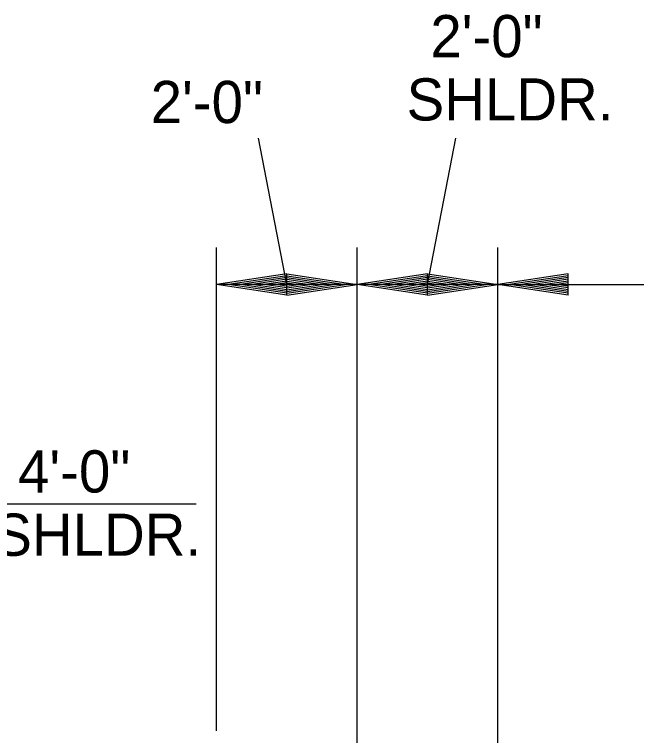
# Model space of a CAD drawing. Extents: x 2829243 to 2838161, y 467639 to 474695.
# Drawn here: x 2833956.1 to 2834044.6, y 469093.4 to 469196 of the extents above; entities that cross this region are included whole.
import ezdxf

# ---------------------------------------------------------------- set-up
doc = ezdxf.new("R2010")
doc.units = 0
doc.layers.add('R_Dimension', color=7, linetype='Continuous')

msp = doc.modelspace()

# ---------------------------------------------------------------- linework, layer by layer
at = {"layer": 'R_Dimension'}
for p, q in [((2833994.82, 469157.58), (2833990.77, 469178.39)), ((2834014.82, 469157.58), (2834018.87, 469178.39)), ((2833984.82, 469094.1), (2833984.82, 469162.83)), ((2834004.82, 469086.56), (2834004.82, 469162.83)), ((2834024.82, 469065.85), (2834024.82, 469162.83)), ((2833994.82, 469159.08), (2833984.82, 469157.58)), ((2833994.82, 469158.83), (2833986.49, 469157.58)), ((2833994.82, 469156.08), (2833994.82, 469159.08)), ((2833994.82, 469159.08), (2834004.82, 469157.58)), ((2833994.82, 469156.08), (2833994.82, 469159.08)), ((2833994.82, 469158.83), (2834003.15, 469157.58)), ((2834014.82, 469159.08), (2834004.82, 469157.58)), ((2834014.82, 469158.83), (2834006.49, 469157.58)), ((2834014.82, 469156.08), (2834014.82, 469159.08)), ((2834014.82, 469159.08), (2834024.82, 469157.58)), ((2834014.82, 469156.08), (2834014.82, 469159.08)), ((2834014.82, 469158.83), (2834023.15, 469157.58)), ((2834034.82, 469159.08), (2834024.82, 469157.58)), ((2834034.82, 469158.83), (2834026.49, 469157.58)), ((2834034.82, 469156.08), (2834034.82, 469159.08)), ((2834004.82, 469157.58), (2833984.82, 469157.58)), ((2833994.82, 469156.08), (2833984.82, 469157.58)), ((2833994.82, 469156.33), (2833986.49, 469157.58)), ((2833994.82, 469158.57), (2833988.21, 469157.58)), ((2833994.82, 469156.58), (2833988.21, 469157.58)), ((2833994.82, 469158.32), (2833989.88, 469157.58)), ((2833994.82, 469156.83), (2833989.88, 469157.58)), ((2833994.82, 469158.07), (2833991.57, 469157.58)), ((2833994.82, 469157.09), (2833991.57, 469157.58)), ((2833994.82, 469157.81), (2833993.24, 469157.58)), ((2833994.82, 469157.34), (2833993.24, 469157.58)), ((2833994.82, 469158.57), (2834001.43, 469157.58)), ((2833994.82, 469158.32), (2833999.77, 469157.58)), ((2833994.82, 469158.07), (2833998.07, 469157.58)), ((2833994.82, 469157.81), (2833996.4, 469157.58)), ((2833994.82, 469156.08), (2834004.82, 469157.58)), ((2833994.82, 469157.09), (2833998.07, 469157.58)), ((2833994.82, 469156.58), (2834001.43, 469157.58)), ((2833994.82, 469156.33), (2834003.15, 469157.58)), ((2833994.82, 469156.83), (2833999.77, 469157.58)), ((2833994.82, 469157.34), (2833996.4, 469157.58)), ((2834024.82, 469157.58), (2834004.82, 469157.58)), ((2834014.82, 469156.08), (2834004.82, 469157.58)), ((2834014.82, 469156.33), (2834006.49, 469157.58)), ((2834014.82, 469158.57), (2834008.21, 469157.58)), ((2834014.82, 469156.58), (2834008.21, 469157.58)), ((2834014.82, 469158.32), (2834009.88, 469157.58)), ((2834014.82, 469156.83), (2834009.88, 469157.58)), ((2834014.82, 469158.07), (2834011.57, 469157.58)), ((2834014.82, 469157.09), (2834011.57, 469157.58)), ((2834014.82, 469157.81), (2834013.24, 469157.58)), ((2834014.82, 469157.34), (2834013.24, 469157.58)), ((2834014.82, 469158.57), (2834021.43, 469157.58)), ((2834014.82, 469158.32), (2834019.77, 469157.58)), ((2834014.82, 469158.07), (2834018.07, 469157.58)), ((2834014.82, 469157.81), (2834016.4, 469157.58)), ((2834014.82, 469156.08), (2834024.82, 469157.58)), ((2834014.82, 469157.09), (2834018.07, 469157.58)), ((2834014.82, 469156.58), (2834021.43, 469157.58)), ((2834014.82, 469156.33), (2834023.15, 469157.58)), ((2834014.82, 469156.83), (2834019.77, 469157.58)), ((2834014.82, 469157.34), (2834016.4, 469157.58)), ((2834034.82, 469156.08), (2834024.82, 469157.58)), ((2834024.82, 469157.58), (2834174.82, 469157.58)), ((2834034.82, 469156.33), (2834026.49, 469157.58)), ((2834034.82, 469158.57), (2834028.21, 469157.58)), ((2834034.82, 469156.58), (2834028.21, 469157.58)), ((2834034.82, 469158.32), (2834029.88, 469157.58)), ((2834034.82, 469156.83), (2834029.88, 469157.58)), ((2834034.82, 469158.07), (2834031.57, 469157.58)), ((2834034.82, 469157.09), (2834031.57, 469157.58)), ((2834034.82, 469157.81), (2834033.24, 469157.58)), ((2834034.82, 469157.34), (2834033.24, 469157.58)), ((2833981.89, 469126.32), (2833941.9, 469126.32))]:
    msp.add_line(p, q, dxfattribs=at)

# ---------------------------------------------------------------- texts
for s, p in [('2\'-0"', (2834015.23, 469189.92)), ('2\'-0"', (2833975.44, 469180.55)), ('SHLDR.', (2834011.85, 469180.92)), ('4\'-0"', (2833956.57, 469127.99)), ('SHLDR.', (2833953.19, 469118.99))]:
    msp.add_text(s, height=6, dxfattribs=at).set_placement(p)

doc.saveas('drawing.dxf')
